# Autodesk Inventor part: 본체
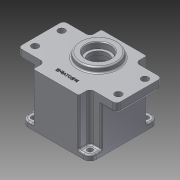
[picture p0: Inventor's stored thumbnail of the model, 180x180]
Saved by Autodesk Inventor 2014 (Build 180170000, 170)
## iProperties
Created: 2015-07
Part Number: 본체
Material: 알루미늄 6061
Document SubType Name: Modeling
Designer: Administrator
Density: 2.71 g/cm^3
Appearance: 알루미늄 - 평지
Mass: 704.561 g
Surface Area: 673.056 cm^2
Volume: 259.985 cm^3
Author: Administrator
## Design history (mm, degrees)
sketch "스케치1"
  geometry: L1 (-45, 45)-(45, 45); L2 (45, 45)-(45, -45); L3 (45, -45)-(-45, -45); L4 (-45, -45)-(-45, 45); L5 (-45, 45)-(45, -45); L6 (45, 45)-(-45, -45); 1 further point
  constraints: 12 end point, 2 midpoint, 2 parallel, 1 horizontal, 1 perpendicular
  dimensions: "d0" = 90 distance of L2.end L3.end; "d1" = 90 distance of L1.end L2.end
extrude "돌출1" new body sketch "스케치1" distance "d2" = 7; taper "d3" = 0 deg
sketch "스케치2"
  geometry: L1 (-30, 45)-(30, 45); L2 (30, 45)-(30, -45); L3 (30, -45)-(-30, -45); L4 (-30, -45)-(-30, 45); L5 (-30, 45)-(30, -45); L6 (30, 45)-(-30, -45); 3 further points
  constraints: 12 end point, 3 midpoint, 2 parallel, 1 coincident, 1 horizontal, 1 perpendicular
  dimensions: "d4" = 60 distance of L1.start L1.end; "d5" = 90 distance of L1.end L2.end
extrude "돌출2" join sketch "스케치2" distance "d6" = 63; taper "d7" = 0 deg
sketch "스케치3"
  geometry: L1 (-65, 30)-(65, 30); L2 (65, 30)-(65, -30); L3 (65, -30)-(-65, -30); L4 (-65, -30)-(-65, 30); L5 (-65, 30)-(65, -30); L6 (65, 30)-(-65, -30); 1 further point
  constraints: 12 end point, 2 midpoint, 2 parallel, 1 horizontal, 1 perpendicular
  dimensions: "d8" = 130 distance of L2.end L3.end; "d9" = 60 distance of L1.end L2.end
extrude "돌출3" join sketch "스케치3" distance "d10" = 12; taper "d11" = 0 deg
sketch "스케치4"
  geometry: L1 (-45, 30)-(45, 30); L2 (45, 30)-(45, -30); L3 (45, -30)-(-45, -30); L4 (-45, -30)-(-45, 30); L5 (-45, 30)-(45, -30); L6 (45, 30)-(-45, -30); 1 further point
  constraints: 12 end point, 2 midpoint, 2 parallel, 1 horizontal, 1 perpendicular
  dimensions: "d12" = 60 distance of L1.end L2.end; "d13" = 90 distance of L2.end L3.end
extrude "돌출4" join sketch "스케치4" distance "d14" = 63; taper "d15" = 0 deg
sketch "스케치5"
  geometry: C1 r 40 at (0, 0); 1 further point
  constraints: 1 centre point, 1 coincident
  dimensions: "d16" = 80 diameter of C1
extrude "돌출5" cut sketch "스케치5" distance "d17" = 9; taper "d18" = 0 deg
sketch "스케치6"
  geometry: C1 r 40 at (0, 0) reference; C2 r 39 at (0, 0)
  constraints: 1 centre point, 1 coincident
  dimensions: "d19" = 78 diameter of C2
extrude "돌출6" cut sketch "스케치6" distance "d20" = 52; taper "d21" = 0 deg
sketch "스케치7"
  geometry: C1 r 39 at (0, 0) reference; C2 r 20.5 at (0, 11); C3 r 14 at (0, -20)
  constraints: 2 centre point, 2 vertical alignment
  dimensions: "d22" = 11 distance of C1.centre C2.centre; "d23" = 20.5 radius of C2; "d24" = 28 diameter of C3; "d25" = 20 distance of C1.centre C3.centre
extrude "돌출7" join sketch "스케치7" distance "d26" = 7; taper "d27" = 0 deg
sketch "스케치8"
  geometry: C1 r 17.5 at (0, 11); A1 r 20.5 centre (0, 11) between (7.402, -8.117) and (-7.402, -8.117) reference; 1 further point
  constraints: 1 centre point, 1 coincident
  dimensions: "d30" = 35 diameter of C1
extrude "돌출8" cut sketch "스케치8" distance "d31" = 10; taper "d32" = 0 deg
sketch "스케치9"
  geometry: C1 r 11 at (0, -20); A1 r 14 centre (0, -20) between (-7.402, -8.117) and (7.402, -8.117) reference; 1 further point
  constraints: 1 centre point, 1 coincident
  dimensions: "d33" = 22 diameter of C1
extrude "돌출9" cut sketch "스케치9" distance "d34" = 7; taper "d35" = 0 deg
sketch "스케치10"
  geometry: C1 r 17.5 at (0, 0) reference; C2 r 12.5 at (0, 0); 1 further point
  constraints: 1 centre point, 1 coincident
  dimensions: "d36" = 25 diameter of C2
extrude "돌출10" cut sketch "스케치10" distance "d37" = 5; taper "d38" = 0 deg
sketch "스케치11"
  geometry: C1 r 11 at (0, 0) reference; C2 r 9.5 at (0, 0); 1 further point
  constraints: 1 centre point, 1 coincident
  dimensions: "d39" = 19 diameter of C2
extrude "돌출11" cut sketch "스케치11" distance "d40" = 1; taper "d41" = 0 deg
sketch "스케치12"
  geometry: C1 r 25 at (0, 11); 1 further point
  constraints: 1 centre point, 1 vertical alignment
  dimensions: "d42" = 50 diameter of C1; "d43" = 11 distance of point (0, 0) C1.centre
extrude "돌출12" join sketch "스케치12" distance "d44" = 7; taper "d45" = 0 deg
sketch "스케치13"
  geometry: C1 r 25 at (0, 0) reference; C2 r 16 at (0, 0); 1 further point
  constraints: 1 centre point, 1 coincident
  dimensions: "d46" = 32 diameter of C2
extrude "돌출13" cut sketch "스케치13" distance "d47" = 8; taper "d48" = 0 deg
sketch "스케치14"
  geometry: L1 (0, 0)-(39, 0); L2 (0, 0)-(24.749, 24.749); L3 (27.411, 21.763)-(30.401, 24.429); L4 (21.763, 27.411)-(24.429, 30.401); A1 r 39 centre (0, 0) between (39, 0) and (30.256, 24.608) reference; A2 r 35 centre (0, 0) between (24.749, 24.749) and (27.411, 21.763); A3 r 4 centre (24.749, 24.749) between (27.411, 21.763) and (21.763, 27.411); 1 further point
  constraints: 10 point on circle, 8 end point, 2 centre point, 2 coincident, 2 tangent, 1 horizontal
  dimensions: "d49" = 70 diameter of A2; "d50" = 45 deg angle of L1 L2; "d51" = 8 diameter of A3
extrude "돌출14" join sketch "스케치14" stored distance "d52" = 8; taper "d53" = 0 deg
sketch "스케치15"
  geometry: A1 r 4 centre (24.749, -24.749) between (27.411, -21.763) and (21.763, -27.411) reference; A2 r 4 centre (-24.749, -24.749) between (-21.763, -27.411) and (-27.411, -21.763) reference; A3 r 4 centre (-24.749, 24.749) between (-27.411, 21.763) and (-21.763, 27.411) reference; A4 r 4 centre (24.749, 24.749) between (21.763, 27.411) and (27.411, 21.763) reference; 4 further points
  constraints: 4 coincident
hole "구멍1" sketch "스케치15" at (-24.749, 24.749), (24.749, 24.749), (24.749, -24.749), (-24.749, -24.749) diameter "d57" = 3.459; stored, may be unused: countersink angle "d61" = 90 deg, drill point angle "d63" = 118 deg; dims "d58" = 12, "d59" = 4, "d60" = 2, "d62" = 15
fillet "모깎기1" dims "d64" = 8
sketch "스케치16"
  geometry: L1 (-45, 37)-(-45, 30) reference; L2 (-45, 30)-(-30, 30) reference; L3 (-30, 30)-(-30, 45) reference; L4 (-30, 45)-(-37, 45) reference; L5 (37, 45)-(30, 45) reference; L6 (30, 45)-(30, 30) reference; L7 (30, 30)-(45, 30) reference; L8 (45, 30)-(45, 37) reference; L9 (-37, -45)-(-30, -45) reference; L10 (-30, -45)-(-30, -30) reference; L11 (-30, -30)-(-45, -30) reference; L12 (-45, -30)-(-45, -37) reference; C1 r 3.5 at (37, -37); C2 r 3.5 at (37, 37); C3 r 3.5 at (-37, 37); C4 r 3.5 at (-37, -37); A1 r 8 centre (37, -37) between (37, -45) and (45, -37) reference; A2 r 8 centre (-37, 37) between (-37, 45) and (-45, 37) reference; A3 r 8 centre (37, 37) between (45, 37) and (37, 45) reference; A4 r 8 centre (-37, -37) between (-45, -37) and (-37, -45) reference; 1 further point
  constraints: 4 centre point, 4 coincident
  dimensions: "d65" = 7 diameter of C1; "d66" = 7 diameter of C2; "d67" = 7 diameter of C3; "d68" = 7 diameter of C4
extrude "돌출15" cut sketch "스케치16" stored distance "d69" = 8; taper "d70" = 0 deg
fillet "모깎기2" dims "d71" = 5
sketch "스케치17"
  geometry: C1 r 4.5 at (-55, 17.5); C2 r 4.5 at (-55, -17.5); C3 r 4.5 at (55, 17.5); C4 r 4.5 at (55, -17.5); 1 further point
  constraints: 4 centre point, 2 horizontal alignment, 2 vertical alignment
  dimensions: "d72" = 9 diameter of C1; "d73" = 9 diameter of C2; "d74" = 9 diameter of C4; "d75" = 9 diameter of C3; "d76" = 110 distance of C3.centre C1.centre; "d77" = 55 horizontal distance of point (0, 0) C1.centre; "d78" = 35 distance of C4.centre C3.centre; "d79" = 17.5 vertical distance of point (0, 0) C3.centre
extrude "돌출16" cut sketch "스케치17" stored distance "d80" = 8; taper "d81" = 0 deg
sketch "스케치18"
  geometry: L1 (-30, -45)-(30, -45) reference; 2 further points
  constraints: 1 vertical alignment, 1 other
  dimensions: "d82" = 15 distance from line of L1 point (0, -30)
feature "엠보싱1" sketch "스케치18" dims "d8" = 130, "d9" = 60, "d83" = 0.5, "d84" = 0
fillet "모깎기3" dims "d85" = 3.5
fillet "모깎기4" dims "d86" = 3
fillet "모깎기5" dims "d87" = 0.3
fillet "모깎기6" dims "d88" = 0.3
fillet "모깎기7" dims "d89" = 0.3
fillet "모깎기8" dims "d90" = 3
fillet "모깎기9" dims "d91" = 3
fillet "모깎기10" dims "d92" = 2
fillet "모깎기11" dims "d93" = 2
fillet "모깎기12" dims "d94" = 2
fillet "모깎기13" dims "d95" = 5
chamfer "모따기1" distance "d96" = 1; stored, may be unused: second distance "d97" = 2, angle "d98" = 45 deg
node "솔리드1"
pattern_circular "원형 패턴1" dims angle "d55" = 360 deg
node "투영된 루프1"
node "투영된 루프2"
node "투영된 루프3"
